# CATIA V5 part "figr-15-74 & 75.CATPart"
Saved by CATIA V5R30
Part number: Part1
Bounding box of the stored display mesh (mm): x -68.209 to 30, y -98.209 to 60, z 0 to 98
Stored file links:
  D:\PROJECTS\CATIA V56R 2020\Resources\Parts File\c15_catia_v5_6r2020_prt\figr-15-74 & 75.CATPart
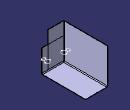
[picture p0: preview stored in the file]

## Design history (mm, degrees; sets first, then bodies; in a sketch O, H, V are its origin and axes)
SheetMetalParameters1: Thickness 1, BendRadius 2, KFactor 0.400515 {= log(min(100,max(20*SheetMetalParameters1.BendRadius,SheetMetalParameters1.Thickness)/SheetMetalParameters1.Thickness))/log(100)/2}, ReliefRadialLength 1, ReliefAxialLength 2, MinimumBendRadius 0
Body1 (main body)
  Sketch1 on xy-plane, origin (0, 0, 0), H (1, 0, 0), V (0, 1, 0)
    line L1 (-30, 60) -> (30, 60)
    line L2 (30, 60) -> (30, -60)
    line L3 (30, -60) -> (-30, -60)
    line L4 (-30, -60) -> (-30, 60)
    length L2 = 120
    length L1 = 60
    distance V L2 = 30
    distance H L1 = 60
    horizontal: L1 H, L3 H
    vertical: L2 V, L4 V
  Wall1: Thickness 1, Profile Sketch1
  d_NewWallOnEdge1: NewWallOnEdge_Edge edge [face of Wall1 | face of Wall1], NewWallOnEdge_Length 98, NewWallOnEdge_HeightLimitOffset 0, NewWallOnEdge_WidthOffset1 0, NewWallOnEdge_WidthOffset2 0, NewWallOnEdge_Angle 90, NewWallOnEdge_BendRadiusValue 2 {= SheetMetalParameters1.BendRadius}, NewWallOnEdge_BendTable SheetMetalParameters1, KFacteur 0.400515 {= log(min(100,max(20*d_NewWallOnEdge1.Radius,SheetMetalParameters1.Thickness)/SheetMetalParameters1.Thickness))/log(100)/2}
  d_NewWallOnEdge2: NewWallOnEdge_Edge edge [face of Wall1 | face of Wall1], NewWallOnEdge_Length 63, NewWallOnEdge_HeightLimitOffset 0, NewWallOnEdge_WidthOffset1 0, NewWallOnEdge_WidthOffset2 0, NewWallOnEdge_Angle 90, NewWallOnEdge_BendRadiusValue 2 {= SheetMetalParameters1.BendRadius}, NewWallOnEdge_BendTable SheetMetalParameters1, KFacteur 0.400515 {= log(min(100,max(20*d_NewWallOnEdge2.Radius,SheetMetalParameters1.Thickness)/SheetMetalParameters1.Thickness))/log(100)/2}
  d_NewWallOnEdge3: NewWallOnEdge_Edge edge [face of d_NewWallOnEdge1 | face of d_NewWallOnEdge1], NewWallOnEdge_Length 44, NewWallOnEdge_HeightLimitOffset 0, NewWallOnEdge_WidthOffset1 0, NewWallOnEdge_WidthOffset2 0, NewWallOnEdge_Angle 90, NewWallOnEdge_BendRadiusValue 2 {= SheetMetalParameters1.BendRadius}, NewWallOnEdge_BendTable SheetMetalParameters1, KFacteur 0.400515 {= log(min(100,max(20*d_NewWallOnEdge3.Radius,SheetMetalParameters1.Thickness)/SheetMetalParameters1.Thickness))/log(100)/2}
  Sketch2 on face of d_NewWallOnEdge3, origin (0, -60, 0), H (-1, 0, 0), V (0, 0, 1)
    circle A1 centre (8.1625, 34.9685) radius 4.4696
    circle A2 centre (8.1625, 23.754) radius 6.7449
    tangency: A2 A1
  SHMMapping1: CATSHMMappingContext d_NewWallOnEdge3, CATSHMMappingObject Sketch2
